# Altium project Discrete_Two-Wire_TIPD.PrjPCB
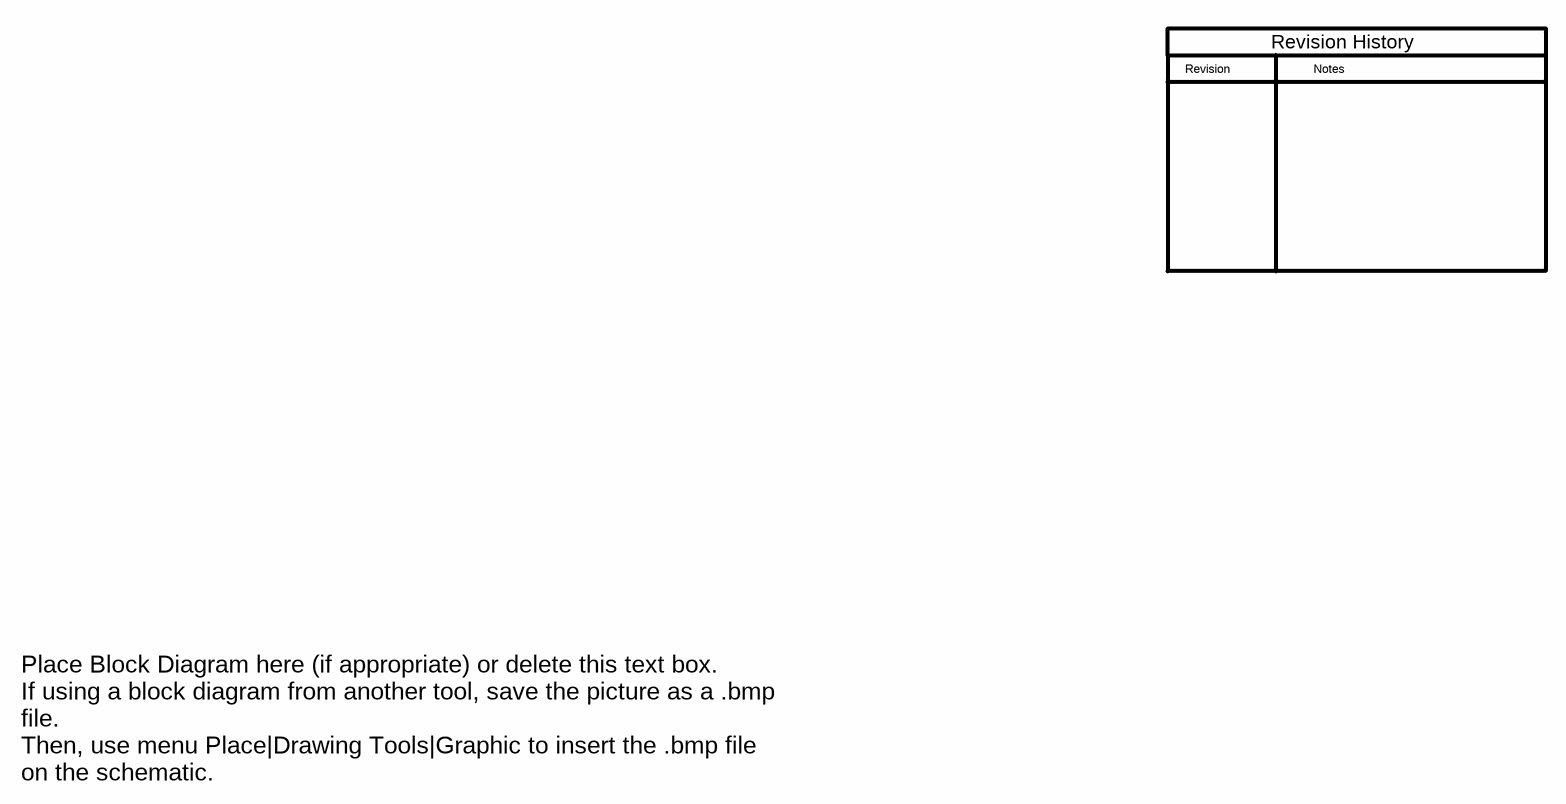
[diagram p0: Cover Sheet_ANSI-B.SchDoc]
CopyrightYear: 2014; PCB_Layout: Who did the Layout?; PCB_Rev: E1; PRJ_Customer: Public Release; PRJ_Engineer: Enter name of project lead; PRJ_Number: XX####; PRJ_Title: Change in menu Project|Project Options|Parameters; SCH_Rev: E1; TechSupport: http://www.ti.com/support
3 sheets, 30 parts. Net scope: global (net labels, ports and power ports of the same name join across sheets).
Board files: Discrete_2-Wire_TIPD_3.PcbDoc, Discrete_2-Wire_TIPD_3_ASCII.PcbDoc
Sheets:
  Cover Sheet_ANSI-B.SchDoc
  Hardware_ANSI-B.SchDoc
  Discrete_2-Wire_AO_3.SchDoc

## Sheet Cover Sheet_ANSI-B.SchDoc
size 431 x 279 mm; Date: Not shown in title block; ApprovedBy: Not shown in title block; CheckedBy: Not shown in title block; Author: Not shown in title block; CompanyName: Not shown in title block; Engineer: Not shown in title block; Organization: Not shown in title block; Address1: Not shown in title block; Address2: Not shown in title block; Address3: Not shown in title block; Address4: Not shown in title block; DocumentNumber: 1; Revision: Use project parameter SCH_Rev; SheetNumber: 1; SheetTotal: 1; PageSetup: Record=PageOptions|CenterHorizontal=True|CenterVertical=True|PrintScale=1.00|XCorrection=1.00|YCorrection=1.00|PrintKind=0|BorderSize=5000000|LeftOffset=0|BottomOffset=0|Orientation=2|PaperLength=1000|PaperWidth=1000|Scale=100|PaperSource=15|PrintQuality=600|MediaType=1|DitherType=10|PaperKind=Letter|PrintScaleMode=1

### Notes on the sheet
- Revision
- Notes
- Revision History
- Place Block Diagram here (if appropriate) or delete this text box.
  If using a block diagram from another tool, save the picture as a .bmp file.
  Then, use menu Place|Drawing Tools|Graphic to insert the .bmp file on the schematic.

## Sheet Hardware_ANSI-B.SchDoc
size 431 x 279 mm; Date: Not shown in title block; ApprovedBy: Not shown in title block; CheckedBy: Not shown in title block; Author: Not shown in title block; CompanyName: Not shown in title block; Engineer: Not shown in title block; Organization: Not shown in title block; Address1: Not shown in title block; Address2: Not shown in title block; Address3: Not shown in title block; Address4: Not shown in title block; DocumentNumber: 1; Revision: Use project parameter SCH_Rev; SheetNumber: 1; SheetTotal: 1; PageSetup: Record=PageOptions|CenterHorizontal=True|CenterVertical=True|PrintScale=1.00|XCorrection=1.00|YCorrection=1.00|PrintKind=0|BorderSize=5000000|LeftOffset=0|BottomOffset=0|Orientation=2|PaperLength=1000|PaperWidth=1000|Scale=100|PaperSource=15|PrintQuality=600|MediaType=1|DitherType=10|PaperKind=Letter|PrintScaleMode=1
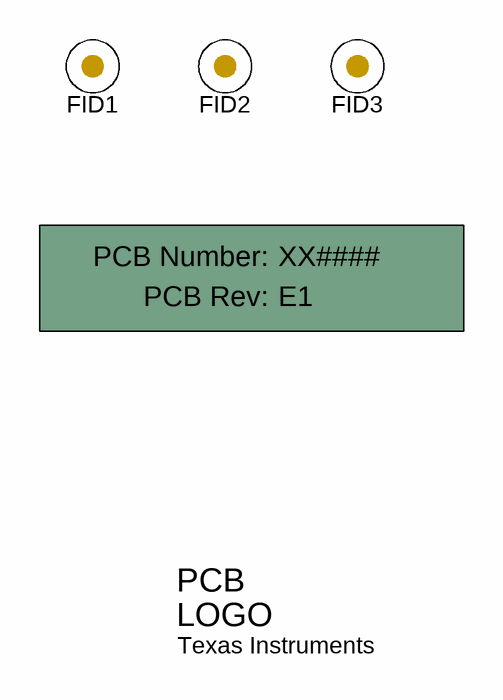
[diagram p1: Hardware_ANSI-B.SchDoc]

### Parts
!PCB  Printed Circuit Board  (value not drawn)  (mechanical)
FID1  Fiducial  [Fiducial10-20]  (value not drawn)
FID2  Fiducial  [Fiducial10-20]  (value not drawn)
FID3  Fiducial  [Fiducial10-20]  (value not drawn)
Logo1  Texas Instruments  [TI_Symbol_Overlay_Small]  (no BOM)

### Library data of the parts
!PCB = PCB: Manufacturer: Any; PartNumber: XX####; SymbolCreator: a0412235
FID1-FID3 = Fiducial: Fiducial mark.  There is nothing to buy or mount.; SymbolCreator: codlsc
Logo1 = TI_Logo: Texas Instrument Corporate Signature; SymbolCreator: codlsc

## Sheet Discrete_2-Wire_AO_3.SchDoc
size 431 x 279 mm; Date: Not shown in title block; ApprovedBy: Not shown in title block; CheckedBy: Not shown in title block; Author: Not shown in title block; CompanyName: Not shown in title block; Engineer: Not shown in title block; Organization: Not shown in title block; Address1: Not shown in title block; Address2: Not shown in title block; Address3: Not shown in title block; Address4: Not shown in title block; DocumentNumber: 1; Revision: Use project parameter SCH_Rev; SheetNumber: 1; SheetTotal: 1; PageSetup: Record=PageOptions|CenterHorizontal=True|CenterVertical=True|PrintScale=1.00|XCorrection=1.00|YCorrection=1.00|PrintKind=0|BorderSize=5000000|LeftOffset=0|BottomOffset=0|Orientation=2|PaperLength=1000|PaperWidth=1000|Scale=100|PaperSource=15|PrintQuality=600|MediaType=1|DitherType=10|PaperKind=Letter|PrintScaleMode=1
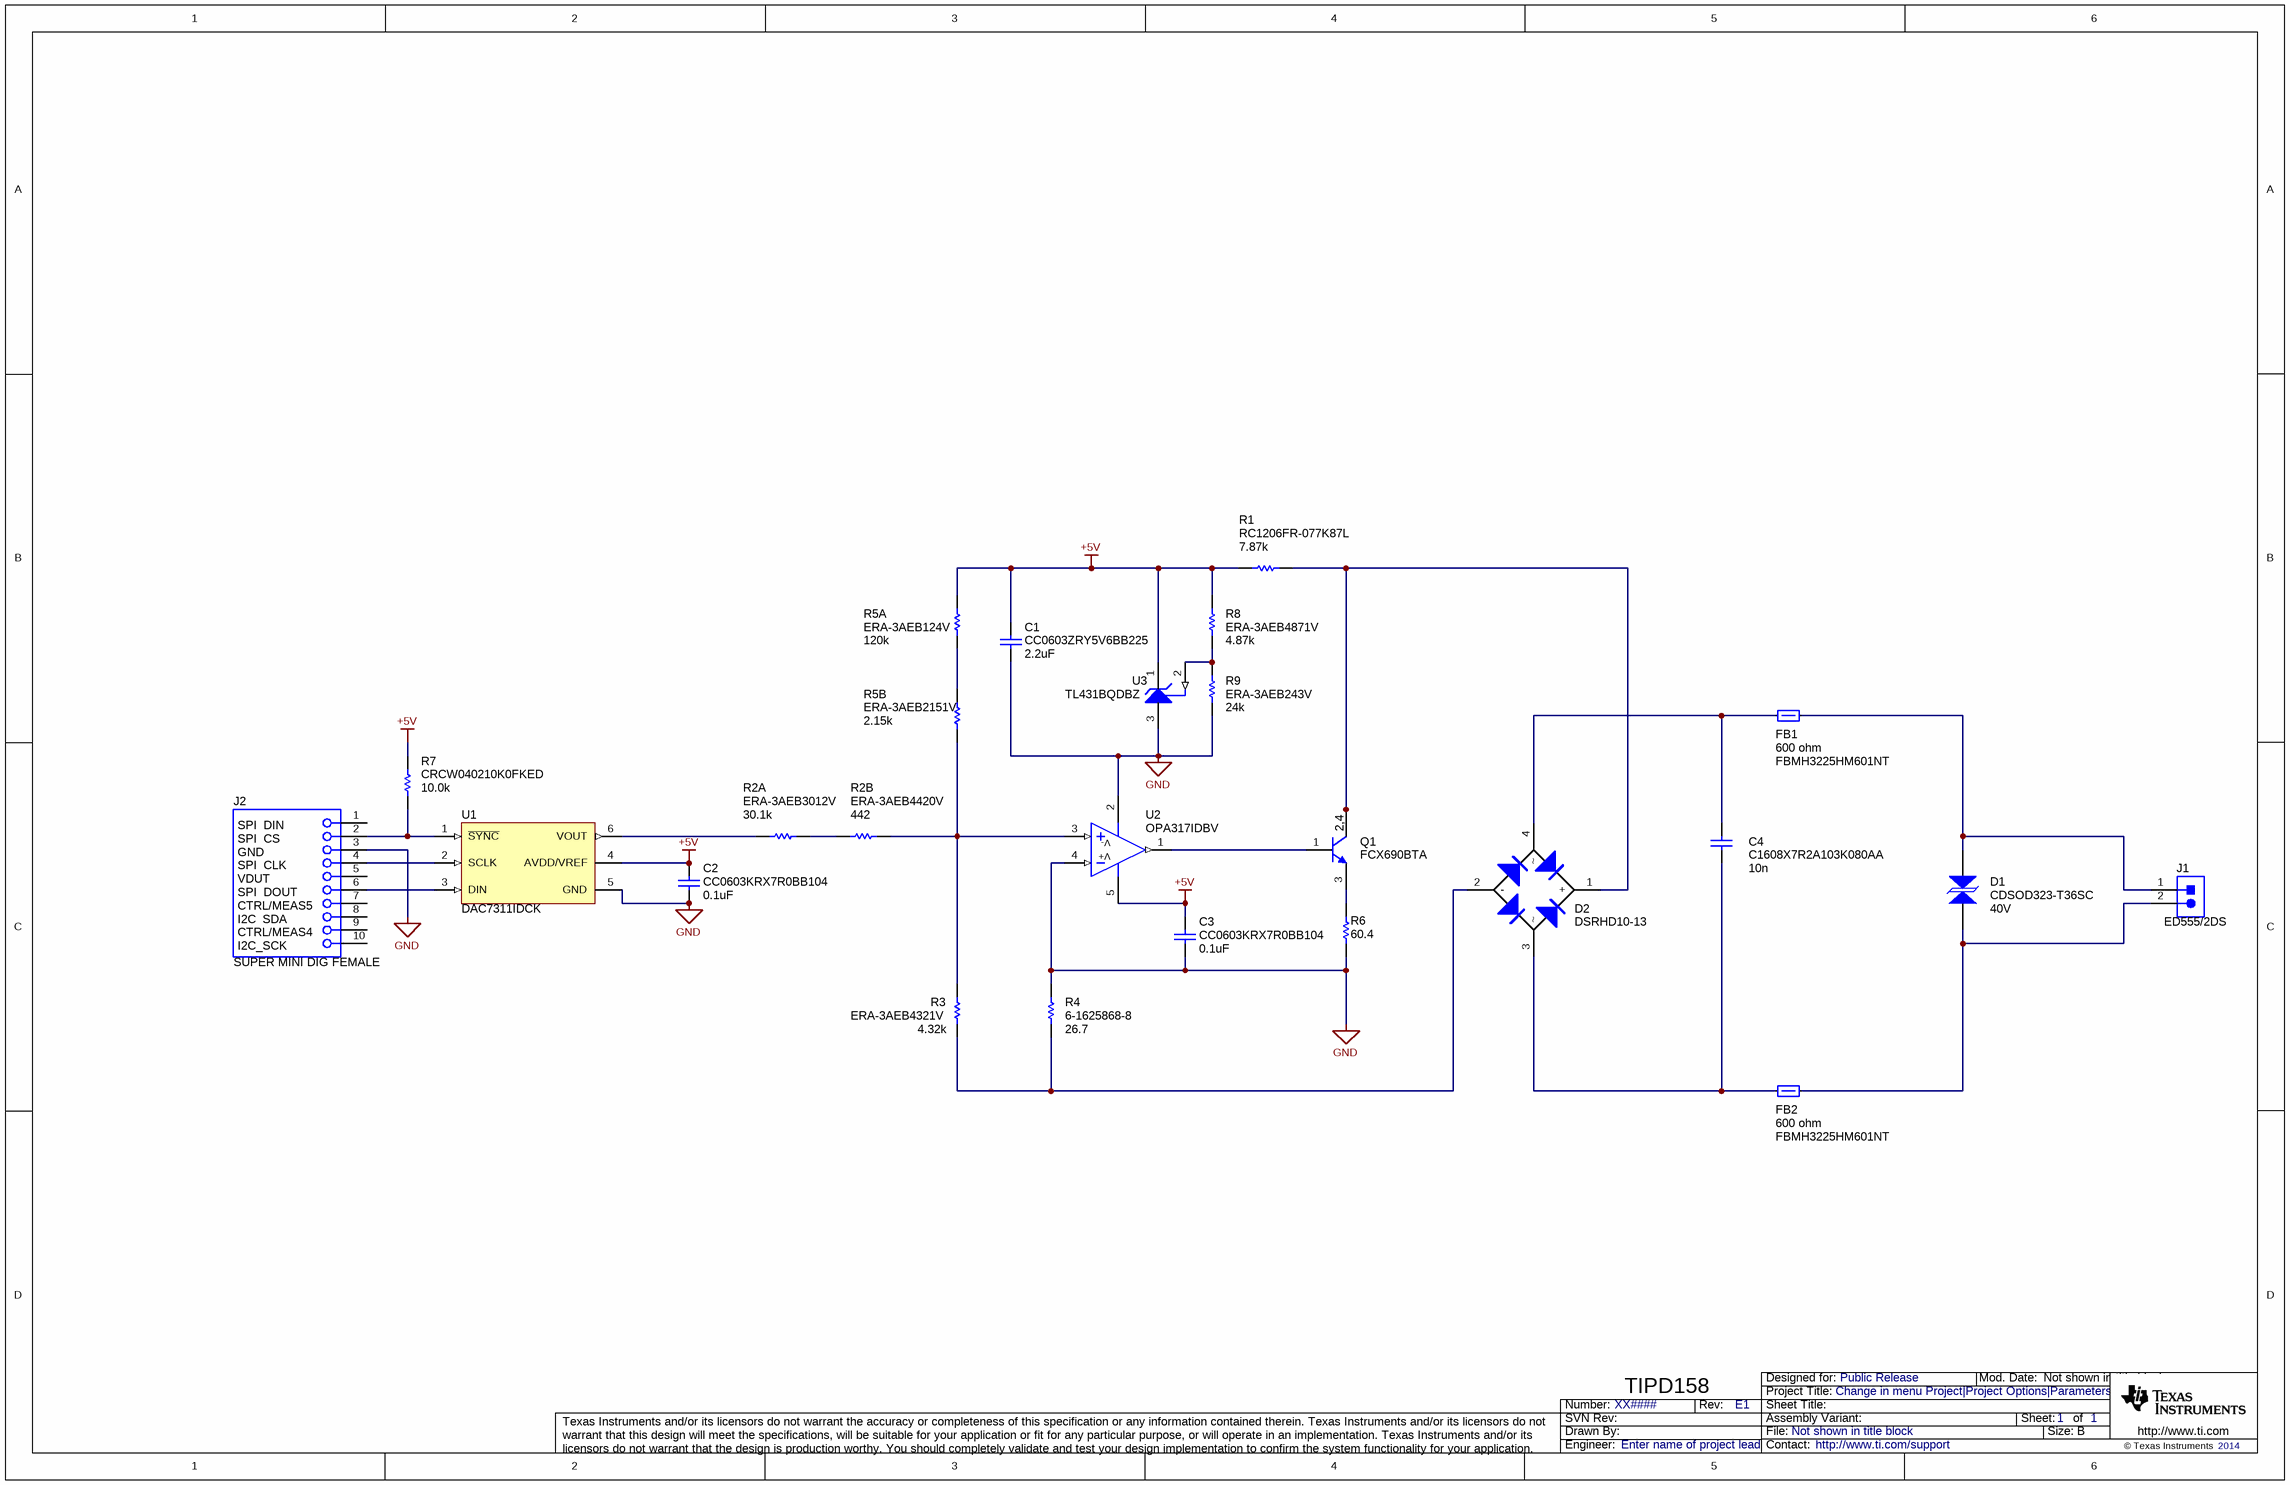
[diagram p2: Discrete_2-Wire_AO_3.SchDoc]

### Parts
C1  CC0603ZRY5V6BB225  value 2.2uF  [0603]
C2  CC0603KRX7R0BB104  value 0.1uF  [0603]
C3  CC0603KRX7R0BB104  value 0.1uF  [0603]
C4  C1608X7R2A103K080AA  value 10n  [0603]
D1  CDSOD323-T36SC  value 40V  [sod-323]
D2  DSRHD10-13  [T-MiniDIP]
FB1  FBMH3225HM601NT  value 600 ohm  [1210_H25]
FB2  FBMH3225HM601NT  value 600 ohm  [1210_H25]
J1  ED555/2DS  [TERM_BLK_ED555-2DS]
J2  SUPER MINI DIG FEMALE  [CONN_851-43-010-20-001000]
Q1  FCX690BTA  [SOT-89-3]
R1  RC1206FR-077K87L  value 7.87k  [1206]
R2A  ERA-3AEB3012V  value 30.1k  [0603]
R2B  ERA-3AEB4420V  value 442  [TBD]
R3  ERA-3AEB4321V  value 4.32k  [0603]
R4  6-1625868-8  value 26.7  [TBD]
R5A  ERA-3AEB124V  value 120k  [0603]
R5B  ERA-3AEB2151V  value 2.15k  [TBD]
R6  ValueDisplayed: 60.4  [0603]  (hidden comment: CRCW060360R4FKEA)
R7  CRCW040210K0FKED  value 10.0k  [0402]
R8  ERA-3AEB4871V  value 4.87k  [TBD]
R9  ERA-3AEB243V  value 24k  [TBD]
U1  DAC7311IDCK  [DCK0006A_N]
U2  OPA317IDBV  [DBV0005A_N]
U3  TL431BQDBZ  [DBZ0003A_N]

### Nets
+5V: C1.1 C2.1 C3.1 R1.1 R5A.2 R7.2 R8.2 U1.4(AVDD/VREF) U2.5(V+) U3.1(CATHODE)
GND: C1.2 C2.2 C3.2 J2.3 R4.2 R6.1 R9.1 U1.5(GND) U2.2(V-) U2.4(IN-) U3.3(ANODE)
NetC4_1: C4.1 D2.4 FB1.1
NetC4_2: C4.2 D2.3 FB2.1
NetD1_1: D1.1 FB1.2 J1.1
NetD1_2: D1.2 FB2.2 J1.2
NetD2_1: D2.1(+) Q1.2(C) Q1.4(C) R1.2
NetD2_2: D2.2(-) R3.1 R4.1
NetJ2_2: J2.2 R7.1 U1.1(~{SYNC})
NetJ2_4: J2.4 U1.2(SCLK)
NetJ2_6: J2.6 U1.3(DIN)
NetQ1_1: Q1.1(B) U2.1(OUT)
NetQ1_3: Q1.3(E) R6.2
NetR2A_1: R2A.1 R2B.1
NetR2A_2: R2A.2 U1.6(VOUT)
NetR2B_2: R2B.2 R3.2 R5B.1 U2.3(IN+)
NetR5A_1: R5A.1 R5B.2
NetR8_1: R8.1 R9.2 U3.2(REF)

Not connected (* = marked no-connect by the designer): J2 1 5 7 8 9 10

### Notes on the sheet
- TIPD158

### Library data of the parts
C1 = Capacitor: CAP CER 2.2UF 10V Y5V 0603; Manufacturer: Yageo; Polarized: N; U/M: EA; Tolerance_%: -20%, +80%; TempCo: Y5V (F)
C2 C3 = Capacitor: CAP CER 0.1UF 100V 10% X7R 0603; Manufacturer: Yageo; Polarized: N; U/M: EA
C4 = Capacitor: CAP CER 10000PF 100V X7R 0603; Manufacturer: TDK; Polarized: N; U/M: EA; Tolerance_%: ±10%
D1 = SMAJ15CA: TVS DIODE 36VWM 60VC SOD323; Manufacturer: Bourns Inc
D2 = DSRHD10-13: Diode, Switching-Bridge, 1000V, 1A, 5.0x1.21x6.2mm; Manufacturer: Diodes Inc.; U/M: EA; Vf_V: 1.15; Value2: 1.15V; Io_A: 1; Vr_V: 1000; TJmax_C: 150
FB1 FB2 = FBMH3225HM601NT: 3A Ferrite Bead, 600 ohm @ 100MHz, SMD; Manufacturer: Taiyo Yuden; Imax_A: 3; DCR_ohm: 0.042; Value1: 0.042 ohm; ZTyp@100MHz_Ohm: 600; U/M: EA
J1 = ED555/2DS: Terminal Block, 6A, 3.5mm Pitch, 2-Pos, TH; Manufacturer: On-Shore Technology; SymbolCreator: a0412235; CompType: Connector; U/M: EA
J2 = 851-43-010-20-001000: Receptacle, 50mil 10x1, R/A, TH; Manufacturer: Mill-Max; SymbolCreator: a0411947; U/M: EA
Q1 = FCX690BTA, Diodes Inc.: Transistor, NPN, 45V, 1A, SOT-89; CompType: BJT; PNP: 0; NPN: 1; Vceo_V: 45; Vcesat1_V: 0.08; Value: 0.08V; TaMin_C: -55; TaMax_C: 150; U/M: EA
R1 = Resistor: RES 7.87K OHM 1/4W 1% 1206 SMD; Manufacturer: Yageo; U/M: EA
R2A = Resistor: RES 30.1K OHM 1/10W .1% 0603 SMD; Manufacturer: Panasonic; U/M: EA
R2B = Resistor: RES 442 OHM 1/10W .1% 0603 SMD; Manufacturer: Panasonic; U/M: EA
R3 = Resistor: RES 4.32K OHM 1/10W .1% 0603 SMD; Manufacturer: Panasonic; U/M: EA; Tolerance_%: ±0.1%; Power_W: 0.1W, 1/10W; TempCo: ±25ppm/°C
R4 = Resistor: RES 26.7 OHM 1/4W 0.1% 0805; Manufacturer: Used in BOM report; U/M: EA
R5A = Resistor: RES 120K OHM 1/10W .1% 0603 SMD; Manufacturer: Panasonic; U/M: EA
R5B = Resistor: RES 2.15K OHM 1/10W .1% 0603 SMD; Manufacturer: Panasonic; U/M: EA
R6 = CRCW060360R4FKEA: RES, 60.4, 1%, 0.1 W, 0603; Manufacturer: Vishay-Dale; CompType: Resistor; Value: 60.4; Value_Code: 60R4; Tolerance_%: 1; Power_W: 0.1; Value2: 0.1W; VDC_V: 75; TempCo: 100 ppm/C; EIA_Code: E96; U/M: EA
R7 = CRCW040210K0FKED: RES, 10.0k ohm, 1%, 0.063W, 0402; Manufacturer: Vishay-Dale; CompType: Resistor; Res_ohm: 10000; Value_Code: 10k0; Tolerance_%: 1; Power_W: 0.063; VDC_V: 50; TempCo: 100 ppm/C; EIA_Code: E96; U/M: EA
R8 = Resistor: RES 4.87K OHM 1/10W .1% 0603 SMD; Manufacturer: Panasonic; U/M: EA
R9 = Resistor: RES 24K OHM 1/10W .1% 0603 SMD; Manufacturer: Panasonic; U/M: EA
U1 = DAC7311IDCK: 2.0V to 5.5V, 80µA, 12-Bit, Low-Power, Single-Channel, Digital-to-Analog Converters in SC70 Package, DCK0006A; Alternate Manufacturer: None; Manufacturer: Texas Instruments; SymbolCreator: a0411947; CompType: IC; U/M: EA
U2 = OPA317IDBV: Low-Offset, Rail-to-Rail I/O Operational Amplifier, DBV0005A; Alternate Manufacturer: None; Manufacturer: Texas Instruments; CompType: IC; U/M: EA
U3 = TL431BQDBZ: PRECISION PROGRAMMABLE REFERENCE, DBZ0003A; Alternate Manufacturer: None; Manufacturer: Texas Instruments; SymbolCreator: a0412235; CompType: IC; U/M: EA

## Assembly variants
001: not fitted FID1 FID2 FID3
